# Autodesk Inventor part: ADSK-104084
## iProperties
Shininess: 27.0
Created: 2001-04
Part Number: ADSK-104084
Document SubType Name: Modeling
Designer: Administrator
Stock Number: ADSK-104084
Density: 1 g/cm^3
Density: 0.0
Volumn: 0.0
Area: 0.0
PropertySet Name: Model Information
Control State: 0
Master: False
Checked Out: False
Author: Administrator
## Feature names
1. Extrusion1
